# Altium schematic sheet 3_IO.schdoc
size 307 x 218 mm; Symbol: Drawing-Symbol_A4; Device: Drawing-Symbol_A4; Company: 嘉立创EDA; Version: V1.0; Page Size: A4; @Project Name: New Project_2025-01-23_00-40-50; @Page Count: 4; @Update Date: 2025-08-03; @Create Date: 2025-07-30; @Schematic Name: Schematic3_7; @Page No: 3; @Page Name: IO; @Create Time: 15:34:36; @Update Time: 01:53:56; Width: 1170; Height: 825; Region Start: 1; X Region Count: 6; Y Region Count: 4; Blade Width: 10; Title Block Position: 3; @Board Name: cm4
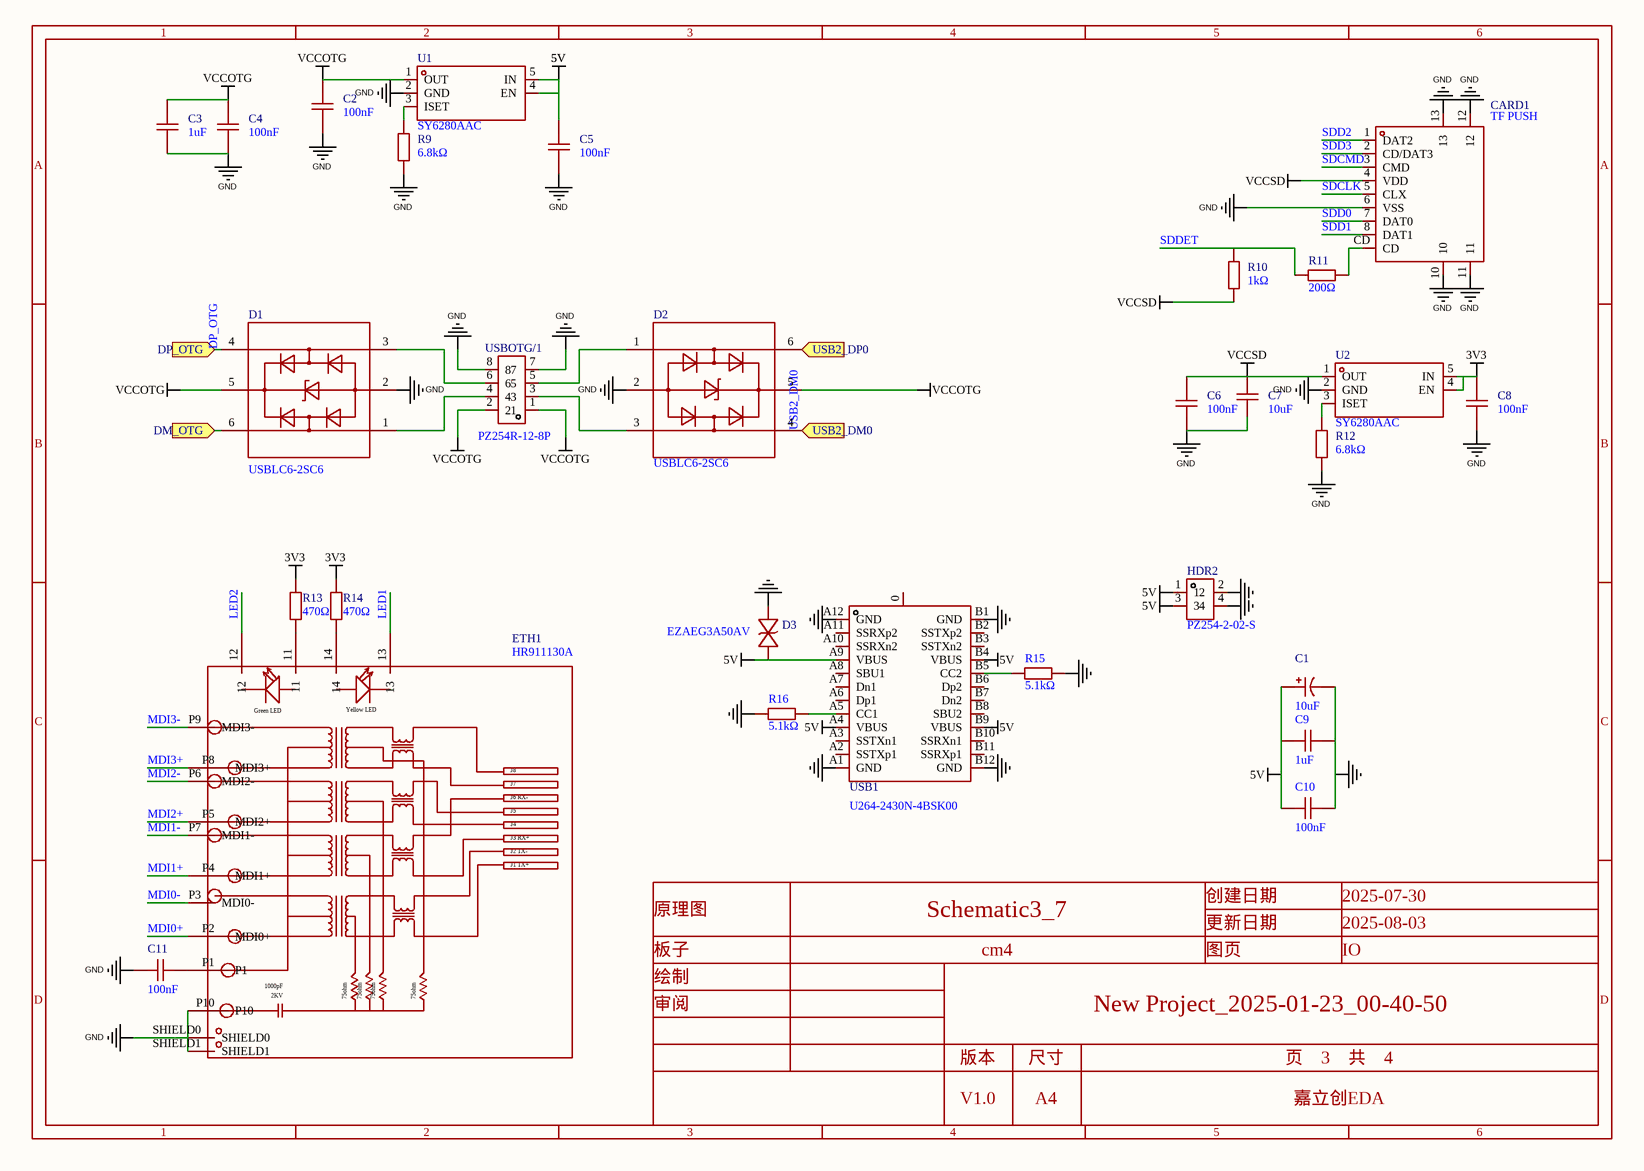
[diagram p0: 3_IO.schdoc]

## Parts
C1  10uF  [CAP-SMD_BD6.3-L6.6-W6.6-LS7.2-FD]
C2  100nF  [C0603]
C3  1uF  [C0603]
C4  100nF  [C0603]
C5  100nF  [C0603]
C6  100nF  [C0603]
C7  10uF  [C0603]
C8  100nF  [C0603]
C9  1uF  [C0603]
C10  100nF  [C0603]
C11  100nF  [C0603]
CARD1  TF PUSH  [TF-SMD_TF-PUSH]
D1  USBLC6-2SC6  [SOT-23-6_L2.9-W1.6-P0.95-LS2.8-BL]
D2  USBLC6-2SC6  [SOT-23-6_L2.9-W1.6-P0.95-LS2.8-BL]
D3  EZAEG3A50AV  [D0603-BI]
ETH1  HR911130A  [RJ45-TH_HR911130A]
HDR2  PZ254-2-02-S  [HDR-SMD_4P-P2.54-V-M-R2-C2-LS7.5]
R9  6.8kΩ  [R0603]
R10  1kΩ  [R0603]
R11  200Ω  [R0603]
R12  6.8kΩ  [R0603]
R13  470Ω  [R0603]
R14  470Ω  [R0603]
R15  5.1kΩ  [R0603]
R16  5.1kΩ  [R0603]
U1  SY6280AAC  [SOT-23-5_L3.0-W1.7-P0.95-LS2.8-BL]
U2  SY6280AAC  [SOT-23-5_L3.0-W1.7-P0.95-LS2.8-BL]
USB1  U264-2430N-4BSK00  [USB-C-SMD_HC-TYPE-C-24P-FLS-CH5.06-5A-23]
USBOTG/1  PZ254R-12-8P  [HDR-TH_8P-P2.54-H-M-R2-C4-S2.54]

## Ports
DM_OTG (in), DP_OTG (in), USB2_DM0 (in), USB2_DP0 (in)

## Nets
3V3: C8.2 R13.2 R14.2 U2.4(EN) U2.5(IN)
5V: C1.1 C5.2 C9.1 C10.1 D3.1(K) HDR2.1 HDR2.3 U1.4(EN) U1.5(IN) USB1.A4(VBUS) USB1.A9(VBUS) USB1.B4(VBUS) USB1.B9(VBUS)
GND: C1.2 C2.1 C3.1 C4.1 C5.1 C6.1 C7.2 C8.1 C9.2 C10.2 C11.1 CARD1.6(VSS) CARD1.10 CARD1.11 CARD1.12 CARD1.13 D1.2 D2.2 D3.2(A) ETH1.P10 ETH1.SHIELD0 ETH1.SHIELD1 HDR2.2 HDR2.4 R9.1 R12.1 R15.2 R16.1 U1.2(GND) U2.2(GND) USB1.A1(GND) USB1.A12(GND) USB1.B1(GND) USB1.B12(GND) USBOTG/1.7 USBOTG/1.8
VCCOTG: C2.2 C3.2 C4.2 D1.5 D2.5 U1.1(OUT) USBOTG/1.1 USBOTG/1.2
VCCSD: C6.2 C7.1 CARD1.4(VDD) R10.1 U2.1(OUT)
DM_OTG: D1.6 ; port DM_OTG
DP_OTG: D1.4 ; port DP_OTG
LED1: ETH1.13
LED2: ETH1.12
MDI0+: ETH1.P2(MDI0+)
MDI0-: ETH1.P3(MDI0-)
MDI1+: ETH1.P4(MDI1+)
MDI1-: ETH1.P7(MDI1-)
MDI2+: ETH1.P5(MDI2+)
MDI2-: ETH1.P6(MDI2-)
MDI3+: ETH1.P8(MDI3+)
MDI3-: ETH1.P9(MDI3-)
SDCLK: CARD1.5(CLX)
SDCMD: CARD1.3(CMD)
SDD0: CARD1.7(DAT0)
SDD1: CARD1.8(DAT1)
SDD2: CARD1.1(DAT2)
SDD3: CARD1.2(CD/DAT3)
SDDET: R10.2 R11.1
USB2_DM0: D2.4 ; port USB2_DM0
USB2_DP0: D2.6 ; port USB2_DP0
NetC11_2: C11.2 ETH1.P1
NetCARD1_CD: CARD1.CD R11.2
NetD1_1: D1.1 USBOTG/1.4
NetD1_3: D1.3 USBOTG/1.6
NetD2_1: D2.1 USBOTG/1.5
NetD2_3: D2.3 USBOTG/1.3
NetETH1_11: ETH1.11 R13.1
NetETH1_14: ETH1.14 R14.1
NetR9_2: R9.2 U1.3(ISET)
NetR12_2: R12.2 U2.3(ISET)
NetR15_1: R15.1 USB1.B5(CC2)
NetR16_2: R16.2 USB1.A5(CC1)

Not connected (* = marked no-connect by the designer): USB1 0(SHEELD) A2(SSTXp1) A3(SSTXn1) A6(Dp1) A7(Dn1) A8(SBU1) A10(SSRXn2) A11(SSRXp2) B2(SSTXp2) B3(SSTXn2) B6(Dp2) B7(Dn2) B8(SBU2) B10(SSRXn1) B11(SSRXp1)

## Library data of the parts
C1 = HV1J106M0605PZ: Manufacturer: HONOR(荣誉); Add into BOM: yes; Tolerance: ±20%; Rated Voltage: 63V; φD: 6.3mm; L: 5mm
C2 C4-C6 C8 C11 = CC0603KRX7R9BB104: Manufacturer: YAGEO(国巨); Add into BOM: yes; Tolerance: ±10%; Voltage Rated: 50V; Temperature Coefficient: X7R
C3 = CL10A105KB8NNNC: Manufacturer: SAMSUNG(三星); Symbol: CL10A106KP8NNNC; Add into BOM: yes; Tolerance: ±10%; Voltage Rated: 50V; Temperature Coefficient: X5R
C7 = CL10A106MO8NQNC: Manufacturer: SAMSUNG(三星); Add into BOM: yes; Tolerance: ±20%; Voltage Rated: 16V; Temperature Coefficient: X5R
C9 = CL10A105KB8NNNC: Manufacturer: SAMSUNG(三星); Symbol: Capacitance; Add into BOM: yes; Tolerance: ±10%; Voltage Rated: 50V; Temperature Coefficient: X5R
C10 = CC0603KRX7R9BB104: Manufacturer: YAGEO(国巨); Symbol: Capacitance; Add into BOM: yes; Tolerance: ±10%; Voltage Rated: 50V; Temperature Coefficient: X7R
CARD1 = TF PUSH: Manufacturer: SHOU HAN(首韩); Add into BOM: yes; Card Connection Mode: 自弹式; Card Type: MicroSD卡(TF卡); Connector Type: 卡座; Maximum Body Height: 2mm
D1 D2 = USBLC6-2SC6_C7519: Manufacturer: ST(意法半导体); Add into BOM: yes; polarity: 单向; Reverse Stand-Off Voltage (Vrwm): 5.25V; Maximum Clamping Voltage: 17V; Peak Pulse Current (Ipp)@10/1000us: 5A; Breakdown Voltage: 6V; Number of Lines: 双路; Type: ESD
D3 = EZAEG3A50AV: Manufacturer: PANASONIC(松下); Add into BOM: yes
ETH1 = HR911130A: Manufacturer: HANRUN(汉仁); Add into BOM: yes; Connector Type: RJ45插座; Number of Ports: 1; LED: 带LED
HDR2 = PZ254-2-02-S: Manufacturer: HCTL(华灿天禄); Add into BOM: yes; Pin Structure: 2x2P; Pitch: 2.54mm; Circluar Pins/Square Pins: 方针; Current Rating: 3A; Voltage Rating (Max): 250V
R9 R12 = 0603WAF6801T5E: Manufacturer: UNI-ROYAL(厚声); Add into BOM: yes; Tolerance: ±1%; Power(Watts): 100mW; Overload Voltage (Max): 75V; Temperature Coefficient: ±100ppm/℃
R10 = 0603WAF1001T5E: Manufacturer: UNI-ROYAL(厚声); Add into BOM: yes; Tolerance: ±1%; Power(Watts): 100mW; Overload Voltage (Max): 75V; Temperature Coefficient: ±100ppm/℃
R11 = 0603WAF2000T5E: Manufacturer: UNI-ROYAL(厚声); Add into BOM: yes; Tolerance: ±1%; Power(Watts): 100mW; Overload Voltage (Max): 75V; Temperature Coefficient: ±100ppm/℃
R13 R14 = 0603WAF4700T5E: Manufacturer: UNI-ROYAL(厚声); Add into BOM: yes; Tolerance: ±1%; Power(Watts): 100mW; Overload Voltage (Max): 75V; Temperature Coefficient: ±100ppm/℃
R15 R16 = RT0603BRD075K1L: Manufacturer: YAGEO(国巨); Symbol: 电阻; Add into BOM: yes; Tolerance: ±0.1%; Power(Watts): 100mW; Overload Voltage (Max): 75V; Temperature Coefficient: ±25ppm/℃
U1 U2 = SY6280AAC_C55136: Manufacturer: silergy(矽力杰); Symbol: SY6280AAAC; Add into BOM: yes
USB1 = U264-2430N-4BSK00: Manufacturer: XKB Connection(中国星坤); Add into BOM: yes; Connector Type: Type-C; Gender: 母; Number of Contacts: 24P
USBOTG/1 = PZ254R-12-8P: Manufacturer: XFCN(兴飞); Add into BOM: yes; Pin Structure: 2x4P; Pitch: 2.54mm; Circluar Pins/Square Pins: 方针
